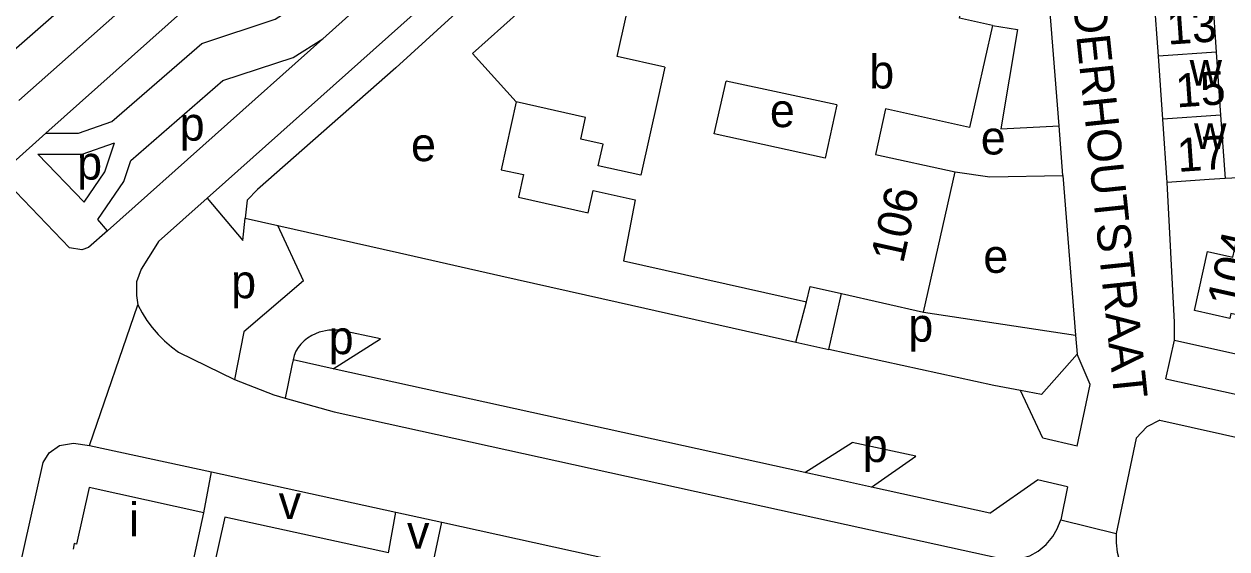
# Model space of a CAD drawing. Extents: x 161775 to 163181, y 382878 to 383925.
# Drawn here: x 162592 to 162735.4, y 383145.8 to 383208.4 of the extents above; entities that cross this region are included whole.
import ezdxf

# ---------------------------------------------------------------- set-up
doc = ezdxf.new("R2010")
doc.units = 0
for name, color, linetype in [('BLT_Basislijn', 7, 'Continuous'), ('BLT_Bebouwing', 7, 'Continuous'), ('BLT_Centroide', 7, 'Continuous'), ('BLT_Huisnummer', 7, 'Continuous'), ('BLT_Huisnummer_ tussenligend', 7, 'Continuous'), ('BLT_Onderverdeling_panden', 7, 'Continuous'), ('BLT_Straatnaam', 7, 'Continuous'), ('BLT_Vlakafsluiter', 7, 'Continuous')]:
    doc.layers.add(name, color=color, linetype=linetype)

msp = doc.modelspace()

# ---------------------------------------------------------------- linework, layer by layer
at = {"layer": 'BLT_Basislijn'}
for p, q in [((162663.13, 383220.74), (162645.43, 383204.86)), ((162632.59, 383211.1), (162627.58, 383206.63)), ((162645.43, 383204.86), (162650.63, 383199.08)), ((162715.82, 383190.32), (162715.36, 383196.23)), ((162599.13, 383187.11), (162593.62, 383192.87)), ((162715.82, 383190.32), (162717.33, 383171.27)), ((162618.34, 383185.21), (162622.22, 383184.34)), ((162625.3, 383177.76), (162622.22, 383184.34)), ((162622.22, 383184.34), (162636.73, 383181.07)), ((162636.73, 383181.07), (162648.8, 383178.36)), ((162625.3, 383177.76), (162618.17, 383171.65)), ((162648.8, 383178.36), (162662.78, 383175.21)), ((162687.91, 383169.56), (162689.4, 383176.22)), ((162662.78, 383175.21), (162683.98, 383170.43)), ((162683.98, 383170.43), (162685.26, 383175.23)), ((162699.21, 383174.01), (162717.33, 383171.27)), ((162618.17, 383171.65), (162617.06, 383165.97)), ((162683.98, 383170.43), (162687.91, 383169.56)), ((162717.33, 383171.27), (162717.51, 383168.98)), ((162728.07, 383166.07), (162729.11, 383170.66)), ((162729.11, 383170.66), (162772.85, 383160.95)), ((162610.38, 383169.25), (162617.06, 383165.97)), ((162717.51, 383168.98), (162713.26, 383164.19)), ((162623.9, 383167.63), (162623.11, 383163.75)), ((162624.05, 383168.32), (162623.9, 383167.63)), ((162628.83, 383167.26), (162624.05, 383168.32)), ((162685.04, 383154.87), (162628.83, 383167.26)), ((162728.07, 383166.07), (162770.96, 383156.57)), ((162713.4, 383158.99), (162710.74, 383164.66)), ((162713.26, 383164.19), (162710.74, 383164.66)), ((162727.36, 383161.11), (162769.37, 383151.8)), ((162717.49, 383158.03), (162713.4, 383158.99)), ((162599.79, 383158.12), (162614.3, 383154.96)), ((162685.04, 383154.87), (162690.68, 383158.47)), ((162698.29, 383156.82), (162690.68, 383158.47)), ((162566.26, 383031.23), (162594.26, 383156.08)), ((162692.99, 383153.13), (162698.29, 383156.82)), ((162613.42, 383150.06), (162614.3, 383154.96)), ((162614.3, 383154.96), (162636.27, 383150.17)), ((162707.11, 383150.04), (162712.78, 383154)), ((162716.36, 383153.16), (162712.78, 383154)), ((162707.11, 383150.04), (162692.99, 383153.13)), ((162716.36, 383153.16), (162715.55, 383149.22)), ((162635.42, 383145.31), (162636.27, 383150.17)), ((162636.27, 383150.17), (162641.79, 383148.96)), ((162640.7, 383143.89), (162641.79, 383148.96)), ((162641.79, 383148.96), (162679.07, 383140.76))]:
    msp.add_line(p, q, dxfattribs=at)
for points in [[(162688.58, 383254.38), (162615.97, 383189.56), (162613.79, 383187.62)], [(162570.01, 383217.65), (162576.23, 383210.37), (162584.08, 383201.25), (162584.73, 383200.63), (162585.13, 383200.67), (162587.16, 383202.14), (162600, 383213.42), (162644.34, 383252.93)], [(162591.34, 383199.25), (162600, 383206.93), (162614.36, 383219.68), (162636.52, 383239.9), (162642.31, 383245.08), (162642.78, 383245.3), (162643.76, 383246.45), (162645.08, 383250.55), (162644.5, 383252.69), (162644.34, 383252.93)], [(162715.36, 383196.23), (162713.47, 383220.29), (162711.88, 383225.76), (162708.73, 383230.62), (162696.65, 383244.05)], [(162594.57, 383195.37), (162621.56, 383219.46), (162634.6, 383231.13)], [(162602.45, 383196.76), (162613.16, 383206.07), (162621.89, 383208.94), (162625.48, 383211.22), (162628.7, 383214.24), (162631.39, 383217.73), (162632.94, 383221.43), (162633.8, 383225.7), (162634.6, 383231.13)], [(162659.92, 383224.15), (162654.65, 383219.37), (162644.81, 383210.89), (162636.3, 383203.14), (162619.78, 383188.65), (162618.57, 383187.37), (162618.34, 383185.21)], [(162707.41, 383208.19), (162710.39, 383207.73), (162708.41, 383195.89), (162715.36, 383196.23)], [(162627.58, 383206.63), (162601.91, 383183.72)], [(162604.69, 383192.09), (162615.68, 383201.64), (162624.04, 383204.38), (162627.58, 383206.63)], [(162594.57, 383195.37), (162598.48, 383195.37), (162602.45, 383196.76)], [(162590.09, 383189.33), (162590.09, 383190.72), (162590.62, 383191.84), (162594.57, 383195.37)], [(162593.62, 383192.87), (162598.91, 383192.87), (162602.75, 383194.22)], [(162599.13, 383187.11), (162601.62, 383190.73), (162602.75, 383194.22)], [(162601.91, 383183.72), (162600.75, 383185.06), (162603.88, 383189.61), (162604.69, 383192.09)], [(162702.97, 383190.75), (162707.08, 383190.14), (162715.82, 383190.32)], [(162597.4, 383181.68), (162590.09, 383189.33)], [(162729.11, 383170.66), (162729.11, 383172.81), (162728.25, 383189.48)], [(162748.23, 383190.26), (162739.9, 383190.21), (162735.14, 383189.96)], [(162613.79, 383187.62), (162607.98, 383182.44), (162607.67, 383181.93), (162605.92, 383179.13), (162605.38, 383177.63), (162605.36, 383175.99), (162605.55, 383174.88)], [(162613.79, 383187.62), (162618.05, 383182.55), (162618.34, 383185.21)], [(162601.91, 383183.72), (162599.66, 383181.71), (162598.87, 383181.44), (162597.4, 383181.68)], [(162605.55, 383174.88), (162606.05, 383173.93), (162606.62, 383173.02), (162607.26, 383172.16), (162607.96, 383171.34), (162608.71, 383170.59), (162609.53, 383169.89), (162610.38, 383169.25)], [(162628.83, 383167.26), (162634.45, 383170.84), (162629.59, 383171.88), (162628.29, 383171.88), (162627.16, 383171.61), (162626.29, 383171.23), (162625.76, 383170.92), (162625.37, 383170.57), (162624.97, 383170.21), (162624.64, 383169.8), (162624.37, 383169.34), (162624.17, 383168.85), (162624.05, 383168.32)], [(162710.74, 383164.66), (162707.57, 383165.26), (162687.91, 383169.56)], [(162717.49, 383158.03), (162719.07, 383165.37), (162717.51, 383168.98)], [(162617.06, 383165.97), (162621.74, 383164.13), (162623.11, 383163.75)], [(162623.11, 383163.75), (162628.94, 383162.12), (162688.36, 383149.02), (162708.45, 383144.63), (162709.5, 383144.51), (162710.74, 383144.62), (162711.87, 383144.96), (162712.88, 383145.5), (162713.83, 383146.28), (162714.61, 383147.26), (162715.11, 383148.16), (162715.55, 383149.22)], [(162727.36, 383161.11), (162725.81, 383160.34), (162724.54, 383158.99), (162722.17, 383147.6)], [(162594.26, 383156.08), (162594.96, 383157.23), (162596.18, 383158.1), (162597.86, 383158.38), (162599.79, 383158.12)], [(162692.99, 383153.13), (162689.43, 383153.91), (162685.04, 383154.87)], [(162722.17, 383147.6), (162722.14, 383146.48), (162722.28, 383145.37), (162722.56, 383144.3), (162722.93, 383143.41), (162723.36, 383142.67), (162724.01, 383141.85), (162724.95, 383141.15), (162725.72, 383140.83), (162742.41, 383137.13), (162763.68, 383132.44), (162764.95, 383132.23), (162766.23, 383132.3), (162767.42, 383132.63), (162768.51, 383133.19), (162769.55, 383134.05), (162770.36, 383135.12), (162770.9, 383136.19), (162771.26, 383137.23)]]:
    msp.add_lwpolyline(points, dxfattribs=at)
at = {"layer": 'BLT_Bebouwing'}
for p, q in [((162727.2, 383204.55), (162726.67, 383212.09)), ((162733.56, 383212.57), (162734.08, 383205.04)), ((162734.08, 383205.04), (162734.61, 383197.5)), ((162727.73, 383197.02), (162727.2, 383204.55)), ((162668.36, 383203.25), (162667.55, 383199.61)), ((162688.87, 383198.72), (162675.65, 383201.58)), ((162728.25, 383189.48), (162727.73, 383197.02)), ((162734.61, 383197.5), (162735.14, 383189.96)), ((162699.21, 383174.01), (162702.97, 383190.75)), ((162689.4, 383176.22), (162699.21, 383174.01)), ((162611.74, 383142.51), (162613.42, 383150.06))]:
    msp.add_line(p, q, dxfattribs=at)
for points in [[(162707.41, 383208.19), (162703.48, 383209.06), (162706.94, 383224.68), (162694.7, 383227.39)], [(162668.36, 383203.25), (162662.67, 383204.51), (162664.73, 383213.79)], [(162707.41, 383208.19), (162704.67, 383196.03), (162694.67, 383198.27), (162693.45, 383192.83), (162702.97, 383190.75)], [(162688.87, 383198.72), (162687.46, 383192.36), (162674.25, 383195.29), (162675.65, 383201.58)], [(162667.55, 383199.61), (162665.5, 383190.35), (162660.42, 383191.47), (162660.99, 383194.05), (162658.33, 383194.64), (162658.9, 383197.24), (162650.63, 383199.08)], [(162650.63, 383199.08), (162648.84, 383191), (162651.5, 383190.41), (162650.9, 383187.71), (162659.21, 383185.87), (162659.8, 383188.54), (162664.83, 383187.42), (162663.43, 383180.12), (162685.26, 383175.23)], [(162735.14, 383189.96), (162733.24, 383189.83), (162728.25, 383189.48)], [(162737.56, 383173.47), (162735.83, 383173.86), (162735.7, 383173.27), (162731.48, 383174.2), (162733.03, 383181.23), (162736.05, 383180.55), (162736.45, 383182.33), (162739.37, 383181.68)], [(162685.26, 383175.23), (162685.67, 383177.06), (162689.4, 383176.22)], [(162613.42, 383150.06), (162599.72, 383153.1), (162598.22, 383146.35), (162597.96, 383146.4), (162597.82, 383145.74)], [(162635.42, 383145.31), (162615.92, 383149.56), (162609.34, 383120.21), (162609.04, 383120.28)]]:
    msp.add_lwpolyline(points, dxfattribs=at)
at = {"layer": 'BLT_Onderverdeling_panden'}
for p, q in [((162734.08, 383205.04), (162727.2, 383204.55)), ((162734.61, 383197.5), (162727.73, 383197.02))]:
    msp.add_line(p, q, dxfattribs=at)
at = {"layer": 'BLT_Vlakafsluiter'}
for p, q in [((162599.79, 383158.12), (162605.55, 383174.88)), ((162715.55, 383149.22), (162722.17, 383147.6))]:
    msp.add_line(p, q, dxfattribs=at)

# ---------------------------------------------------------------- texts
at = {"layer": 'BLT_Centroide'}
for s, p in [('b', (162692.72, 383200.69)), ('w', (162730.91, 383201.03)), ('e', (162680.88, 383196.08)), ('p', (162610.52, 383194.47)), ('w', (162731.44, 383193.48)), ('e', (162638.1, 383192.02)), ('e', (162706.02, 383192.82)), ('p', (162598.3, 383189.82)), ('e', (162706.32, 383178.7)), ('p', (162616.66, 383175.67)), ('p', (162697.38, 383170.49)), ('p', (162628.28, 383169)), ('p', (162691.95, 383156.13)), ('v', (162622.32, 383149.32)), ('i', (162604.49, 383147.28)), ('v', (162637.62, 383145.79))]:
    msp.add_text(s, height=4, dxfattribs=at).set_placement(p)
at = {"layer": 'BLT_Huisnummer'}
for s, rotation, p in [('13', 3.9969, (162728.32, 383205.91)), ('17', 4.0023, (162729.55, 383190.73)), ('106', 77.5195, (162696.76, 383179.72)), ('104', 77.3888, (162736.84, 383174.35))]:
    msp.add_text(s, height=4, rotation=rotation, dxfattribs=at).set_placement(p)
at = {"layer": 'BLT_Huisnummer_ tussenligend'}
msp.add_text('15', height=4, rotation=3.9969, dxfattribs=at).set_placement((162729.37, 383198.42))
at = {"layer": 'BLT_Straatnaam'}
msp.add_text('VAN MINDERHOUTSTRAAT', height=4, rotation=275.9912, dxfattribs=at).set_placement((162714.66, 383232.99))

doc.saveas('drawing.dxf')
